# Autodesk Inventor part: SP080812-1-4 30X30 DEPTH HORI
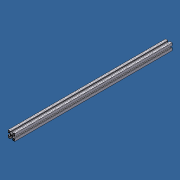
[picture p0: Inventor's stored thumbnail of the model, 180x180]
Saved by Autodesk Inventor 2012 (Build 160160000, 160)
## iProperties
Created: 2012-08
Part Number: SP080812-1-4 30X30 DEPTH HORI
Material: Aluminum-6061
Description: PROFILE 30X30
Document SubType Name: Modeling
Designer: Administrator
Stock Number: 20.1068 PROFILE 30X30
Density: 2.71 g/cm^3
FINISH: CLEAR ANODIZED
Author: Administrator
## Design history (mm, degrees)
sketch "Sketch1"
  geometry: L1 (13.5, -7.8)-(9.3, -7.8) reference; L2 (14, -12.5)-(14, -8.3) reference; L3 (8.3, -14)-(12.5, -14) reference; L4 (7.8, -9.3)-(7.8, -13.5) reference; L5 (-9.3, -7.8)-(-13.5, -7.8) reference; L6 (-7.8, -13.5)-(-7.8, -9.3) reference; L7 (-12.5, -14)-(-8.3, -14) reference; L8 (-14, -8.3)-(-14, -12.5) reference; L9 (3.286, 3.879)-(2.243, 3.657) reference; L10 (3.657, 2.243)-(3.879, 3.286) reference; L11 (3.263, 1.849)-(3.657, 2.243) reference; L12 (3.657, -2.243)-(3.263, -1.849) reference; L13 (3.879, -3.286)-(3.657, -2.243) reference; L14 (2.243, -3.657)-(3.286, -3.879) reference; L15 (1.849, -3.263)-(2.243, -3.657) reference; L16 (-2.243, -3.657)-(-1.849, -3.263) reference; L17 (-3.286, -3.879)-(-2.243, -3.657) reference; L18 (-3.657, -2.243)-(-3.879, -3.286) reference; L19 (-3.263, -1.849)-(-3.657, -2.243) reference; L20 (-3.657, 2.243)-(-3.263, 1.849) reference; L21 (-3.879, 3.286)-(-3.657, 2.243) reference; L22 (-2.243, 3.657)-(-3.286, 3.879) reference; L23 (-1.849, 3.263)-(-2.243, 3.657) reference; L24 (2.243, 3.657)-(1.849, 3.263) reference; L25 (9.3, 7.8)-(13.5, 7.8) reference; L26 (7.8, 13.5)-(7.8, 9.3) reference; L27 (12.5, 14)-(8.3, 14) reference; L28 (14, 8.3)-(14, 12.5) reference; L29 (-8.3, 14)-(-12.5, 14) reference; L30 (-7.8, 9.3)-(-7.8, 13.5) reference; L31 (-13.5, 7.8)-(-9.3, 7.8) reference; L32 (-14, 12.5)-(-14, 8.3) reference; L33 (12.5, 4.1)-(12.5, 6.8) reference; L34 (15, 4.1)-(12.5, 4.1) reference; L35 (15, 15)-(15, 4.1) reference; L36 (4.1, 15)-(15, 15) reference; L37 (4.1, 12.5)-(4.1, 15) reference; L38 (6.8, 12.5)-(4.1, 12.5) reference; L39 (6.8, 7.861)-(6.8, 12.5) reference; L40 (4.639, 5.7)-(6.8, 7.861) reference; L41 (1.497, 5.032)-(4.639, 5.7) reference; L42 (-1.497, 5.032)-(1.497, 5.032) reference; L43 (-4.639, 5.7)-(-1.497, 5.032) reference; L44 (-6.8, 7.861)-(-4.639, 5.7) reference; L45 (-6.8, 12.5)-(-6.8, 7.861) reference; L46 (-4.1, 12.5)-(-6.8, 12.5) reference; L47 (-4.1, 15)-(-4.1, 12.5) reference; L48 (-15, 15)-(-4.1, 15) reference; L49 (-15, 4.1)-(-15, 15) reference; L50 (-12.5, 4.1)-(-15, 4.1) reference; L51 (-12.5, 6.8)-(-12.5, 4.1) reference; L52 (-7.861, 6.8)-(-12.5, 6.8) reference; L53 (-5.7, 4.639)-(-7.861, 6.8) reference; L54 (-5.032, 1.497)-(-5.7, 4.639) reference; L55 (-5.032, -1.497)-(-5.032, 1.497) reference; L56 (-5.7, -4.639)-(-5.032, -1.497) reference; L57 (-7.861, -6.8)-(-5.7, -4.639) reference; L58 (-12.5, -6.8)-(-7.861, -6.8) reference; L59 (-12.5, -4.1)-(-12.5, -6.8) reference; L60 (-15, -4.1)-(-12.5, -4.1) reference; L61 (-15, -15)-(-15, -4.1) reference; L62 (-4.1, -15)-(-15, -15) reference; L63 (-4.1, -12.5)-(-4.1, -15) reference; L64 (-6.8, -12.5)-(-4.1, -12.5) reference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; A1 r 1.5 centre (9.3, -9.3) between (9.3, -7.8) and (7.8, -9.3) reference; A2 r 0.5 centre (13.5, -8.3) between (14, -8.3) and (13.5, -7.8) reference; A3 r 1.5 centre (12.5, -12.5) between (12.5, -14) and (14, -12.5) reference; A4 r 0.5 centre (8.3, -13.5) between (7.8, -13.5) and (8.3, -14) reference; A5 r 0.5 centre (-13.5, -8.3) between (-13.5, -7.8) and (-14, -8.3) reference; A6 r 1.5 centre (-9.3, -9.3) between (-7.8, -9.3) and (-9.3, -7.8) reference; A7 r 0.5 centre (-8.3, -13.5) between (-8.3, -14) and (-7.8, -13.5) reference; A8 r 1.5 centre (-12.5, -12.5) between (-14, -12.5) and (-12.5, -14) reference; A9 r 0.5 centre (3.39, 3.39) between (3.879, 3.286) and (3.286, 3.879) reference; A10 r 0.5 centre (3.39, -3.39) between (3.286, -3.879) and (3.879, -3.286) reference; A11 r 3.75 centre (0, 0) between (-1.849, -3.263) and (1.66, -3.362) reference; A12 r 0.5 centre (-3.39, -3.39) between (-3.879, -3.286) and (-3.286, -3.879) reference; A13 r 3.75 centre (0, 0) between (-3.362, 1.66) and (-3.263, -1.849) reference; A14 r 0.5 centre (-3.39, 3.39) between (-3.286, 3.879) and (-3.879, 3.286) reference; A15 r 0.5 centre (13.5, 8.3) between (13.5, 7.8) and (14, 8.3) reference; A16 r 1.5 centre (9.3, 9.3) between (7.8, 9.3) and (9.3, 7.8) reference; A17 r 0.5 centre (8.3, 13.5) between (8.3, 14) and (7.8, 13.5) reference; A18 r 1.5 centre (12.5, 12.5) between (14, 12.5) and (12.5, 14) reference; A19 r 1.5 centre (-12.5, 12.5) between (-12.5, 14) and (-14, 12.5) reference; A20 r 0.5 centre (-8.3, 13.5) between (-7.8, 13.5) and (-8.3, 14) reference; A21 r 1.5 centre (-9.3, 9.3) between (-9.3, 7.8) and (-7.8, 9.3) reference; A22 r 0.5 centre (-13.5, 8.3) between (-14, 8.3) and (-13.5, 7.8) reference; A23 r 3.75 centre (0, 0) between (-3.263, 1.849) and (-3.362, 1.66) reference; A24 r 3.75 centre (0, 0) between (3.362, 1.66) and (3.263, 1.849) reference; A25 r 3.75 centre (0, 0) between (1.849, 3.263) and (-1.849, 3.263) reference; A26 r 3.75 centre (0, 0) between (1.66, -3.362) and (1.849, -3.263) reference; A27 r 3.75 centre (0, 0) between (3.263, -1.849) and (3.362, 1.66) reference; 2 further points
  constraints: 168 end point, 54 point on circle, 27 centre point, 26 horizontal, 26 vertical, 195 other
extrude "Extrusion1" new body sketch "Sketch1" distance "d2" = 702; taper "d3" = 0 deg
body "Solid1"
